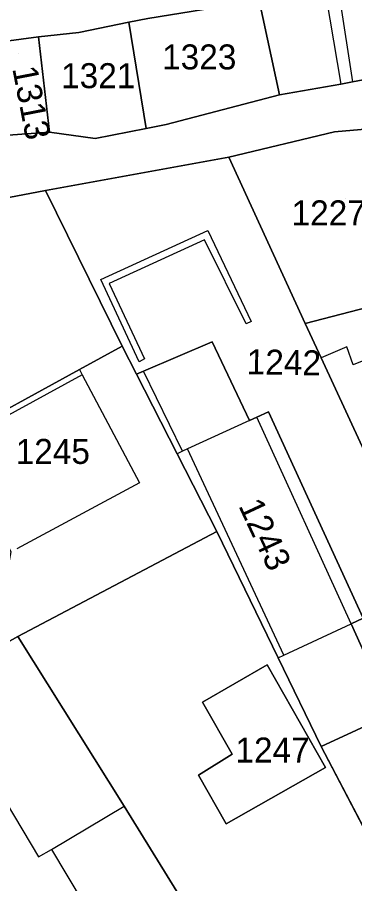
# Model space of a CAD drawing. Extents: x -263943 to -261149, y -1236934 to -1230686.
# Drawn here: x -263034.8 to -263007.8, y -1235384.4 to -1235315.1 of the extents above; entities that cross this region are included whole.
import ezdxf

# ---------------------------------------------------------------- set-up
doc = ezdxf.new("R2010")
doc.units = 0
for name, color, linetype in [('body_kn', 7, 'Continuous'), ('kladpar_druhypozemkov', 7, 'Continuous'), ('kladpar_hranice', 7, 'Continuous'), ('kladpar_parcelnecisla', 7, 'Continuous'), ('kladpar_plochy', 7, 'Continuous'), ('zappar_hrandruhpozemk', 7, 'Continuous')]:
    doc.layers.add(name, color=color, linetype=linetype)

msp = doc.modelspace()

# ---------------------------------------------------------------- linework, layer by layer
at = {"layer": 'body_kn'}
for p, q in [((-263024.4, -1235315.2), (-263024.4, -1235315.2)), ((-263025.91, -1235315.5), (-263025.91, -1235315.5)), ((-263033.14, -1235316.65), (-263033.14, -1235316.65)), ((-263029.91, -1235316.31), (-263029.91, -1235316.31)), ((-263008.93, -1235320.44), (-263008.93, -1235320.44)), ((-263008, -1235320.27), (-263008, -1235320.27)), ((-263008, -1235320.27), (-263008, -1235320.27)), ((-263013.86, -1235321.29), (-263013.86, -1235321.29)), ((-263032.27, -1235324.28), (-263032.27, -1235324.28)), ((-263032.27, -1235324.28), (-263032.27, -1235324.28)), ((-263024.54, -1235323.99), (-263024.54, -1235323.99)), ((-263024.54, -1235323.99), (-263024.54, -1235323.99)), ((-263022.93, -1235323.68), (-263022.93, -1235323.68)), ((-263009.44, -1235324.26), (-263009.44, -1235324.26)), ((-263028.62, -1235324.79), (-263028.62, -1235324.79)), ((-263017.92, -1235326.3), (-263017.92, -1235326.3)), ((-263032.6, -1235328.95), (-263032.6, -1235328.95)), ((-263019.6, -1235332.16), (-263019.6, -1235332.16)), ((-263019.86, -1235332.92), (-263019.86, -1235332.92)), ((-263028.17, -1235336.07), (-263028.17, -1235336.07)), ((-263027.49, -1235336.41), (-263027.49, -1235336.41)), ((-263016.11, -1235339.45), (-263016.11, -1235339.45)), ((-263011.78, -1235339.61), (-263011.78, -1235339.61)), ((-263011.78, -1235339.61), (-263011.78, -1235339.61)), ((-263016.53, -1235339.62), (-263016.53, -1235339.62)), ((-263026.46, -1235341.41), (-263026.46, -1235341.41)), ((-263019.24, -1235341.06), (-263019.24, -1235341.06)), ((-263008.46, -1235341.47), (-263008.46, -1235341.47)), ((-263010.51, -1235342.36), (-263010.51, -1235342.36)), ((-263025.1, -1235342.68), (-263025.1, -1235342.68)), ((-263025.1, -1235342.68), (-263025.1, -1235342.68)), ((-263024.67, -1235342.43), (-263024.67, -1235342.43)), ((-263007.95, -1235342.92), (-263007.95, -1235342.92)), ((-263029.88, -1235343.29), (-263029.88, -1235343.29)), ((-263029.88, -1235343.29), (-263029.88, -1235343.29)), ((-263029.66, -1235343.7), (-263029.66, -1235343.7)), ((-263029.66, -1235343.7), (-263029.66, -1235343.7)), ((-263025.31, -1235343.66), (-263025.31, -1235343.66)), ((-263024.73, -1235343.41), (-263024.73, -1235343.41)), ((-263015.66, -1235347.09), (-263015.66, -1235347.09)), ((-263014.73, -1235346.66), (-263014.73, -1235346.66)), ((-263016.24, -1235347.36), (-263016.24, -1235347.36)), ((-263016.24, -1235347.36), (-263016.24, -1235347.36)), ((-263021.62, -1235349.83), (-263021.62, -1235349.83)), ((-263021.62, -1235349.83), (-263021.62, -1235349.83)), ((-263021.22, -1235349.64), (-263021.22, -1235349.64)), ((-263021.22, -1235349.64), (-263021.22, -1235349.64)), ((-263022.05, -1235350.03), (-263022.05, -1235350.03)), ((-263022.05, -1235350.03), (-263022.05, -1235350.03)), ((-263025.07, -1235352.35), (-263025.07, -1235352.35)), ((-263018.87, -1235356.25), (-263018.87, -1235356.25)), ((-263008.12, -1235363.65), (-263008.12, -1235363.65)), ((-263008.12, -1235363.65), (-263008.12, -1235363.65)), ((-263034.8, -1235364.66), (-263034.8, -1235364.66)), ((-263013.95, -1235366.36), (-263013.95, -1235366.36)), ((-263013.95, -1235366.36), (-263013.95, -1235366.36)), ((-263013.5, -1235366.15), (-263013.5, -1235366.15)), ((-263014.85, -1235366.93), (-263014.85, -1235366.93)), ((-263020.02, -1235369.9), (-263020.02, -1235369.9)), ((-263010.5, -1235373.45), (-263010.5, -1235373.45)), ((-263010.5, -1235373.45), (-263010.5, -1235373.45)), ((-263017.63, -1235374.06), (-263017.63, -1235374.06)), ((-263010.16, -1235375.15), (-263010.16, -1235375.15)), ((-263020.34, -1235375.76), (-263020.34, -1235375.76)), ((-263020.34, -1235375.76), (-263020.34, -1235375.76)), ((-263026.28, -1235378.22), (-263026.28, -1235378.22)), ((-263018.13, -1235379.65), (-263018.13, -1235379.65)), ((-263032.12, -1235381.69), (-263032.12, -1235381.69)), ((-263033.14, -1235382.3), (-263033.14, -1235382.3))]:
    msp.add_line(p, q, dxfattribs=at)
at = {"layer": 'kladpar_druhypozemkov'}
for p, q in [((-263020.36, -1235317.37), (-263020.36, -1235317.37)), ((-263034.75, -1235318.03), (-263034.75, -1235318.03)), ((-263029.56, -1235318.87), (-263029.56, -1235318.87)), ((-263008.57, -1235329.61), (-263008.57, -1235329.61)), ((-263013.46, -1235341.99), (-263013.46, -1235341.99)), ((-263032.34, -1235348.54), (-263032.34, -1235348.54)), ((-263014.11, -1235355.88), (-263014.11, -1235355.88)), ((-263015.04, -1235372.14), (-263015.04, -1235372.14))]:
    msp.add_line(p, q, dxfattribs=at)
at = {"layer": 'kladpar_hranice'}
for points in [[(-263008, -1235320.27), (-263008.93, -1235320.44), (-263013.86, -1235321.29), (-263015.49, -1235313.75), (-263010.22, -1235312.81), (-263002.33, -1235311.36), (-263002.22, -1235312.05), (-263001.13, -1235318.99), (-263008, -1235320.27)], [(-263015.49, -1235313.75), (-263024.4, -1235315.2), (-263025.91, -1235315.5), (-263029.91, -1235316.31), (-263033.14, -1235316.65), (-263036.95, -1235317.16)], [(-263024.54, -1235323.99), (-263025.91, -1235315.5), (-263024.4, -1235315.2), (-263015.49, -1235313.75), (-263013.86, -1235321.29), (-263022.93, -1235323.68), (-263024.54, -1235323.99)], [(-263035.58, -1235324.54), (-263032.27, -1235324.28), (-263028.62, -1235324.79), (-263024.54, -1235323.99), (-263022.93, -1235323.68), (-263013.86, -1235321.29), (-263008.93, -1235320.44), (-263008, -1235320.27), (-263001.13, -1235318.99), (-262996.89, -1235318.14), (-262989.17, -1235316.6), (-262980.34, -1235316.17), (-262972.19, -1235315.65), (-262967.78, -1235315.31), (-262963.87, -1235317.08)], [(-263032.27, -1235324.28), (-263033.14, -1235316.65), (-263029.91, -1235316.31), (-263025.91, -1235315.5), (-263024.54, -1235323.99), (-263028.62, -1235324.79), (-263032.27, -1235324.28)], [(-263035.67, -1235324.12), (-263036.87, -1235317.92), (-263036.95, -1235317.16), (-263033.14, -1235316.65), (-263032.27, -1235324.28), (-263035.58, -1235324.54), (-263035.67, -1235324.12)], [(-262964.37, -1235320.47), (-262977.61, -1235320.74), (-262986.01, -1235321.6), (-262989.92, -1235322.11), (-263003.33, -1235323.74), (-263009.44, -1235324.26), (-263017.92, -1235326.3), (-263032.6, -1235328.95), (-263051.35, -1235332.53)], [(-263011.78, -1235339.61), (-263017.92, -1235326.3), (-263009.44, -1235324.26), (-263003.33, -1235323.74), (-262999.65, -1235335.61), (-262999.65, -1235336.46), (-263011.78, -1235339.61)], [(-263000.82, -1235363.3), (-262999.15, -1235366.91), (-262997.27, -1235369.36), (-263001.69, -1235369.37), (-263004.85, -1235370.83), (-263008.12, -1235363.65), (-263007.14, -1235363.19), (-263014.73, -1235346.66), (-263015.66, -1235347.09), (-263016.24, -1235347.36), (-263019.24, -1235341.06), (-263024.73, -1235343.41), (-263025.31, -1235343.66), (-263026.46, -1235341.41), (-263032.6, -1235328.95), (-263017.92, -1235326.3), (-263011.78, -1235339.61), (-263010.51, -1235342.36), (-263006.23, -1235351.57), (-263000.82, -1235363.3)], [(-263040.01, -1235348.83), (-263042.25, -1235350.05), (-263042.84, -1235348.91), (-263046.17, -1235342.51), (-263048.46, -1235338.09), (-263051.35, -1235332.53), (-263032.6, -1235328.95), (-263026.46, -1235341.41), (-263029.88, -1235343.29), (-263040.01, -1235348.83)], [(-262991.44, -1235359.09), (-262995, -1235360.63), (-263000.38, -1235348.76), (-263001.09, -1235349.1), (-263005.79, -1235351.36), (-263006.23, -1235351.57), (-263010.51, -1235342.36), (-263011.78, -1235339.61), (-262999.65, -1235336.46), (-262998.02, -1235342.31), (-262997.43, -1235342.14), (-262991.44, -1235359.09)], [(-263022.05, -1235350.03), (-263018.87, -1235356.25), (-263034.8, -1235364.66), (-263041.47, -1235368.38), (-263059.41, -1235378.39), (-263061.17, -1235379.37), (-263062.02, -1235377.85), (-263036.34, -1235363.14), (-263035.33, -1235357.88), (-263040.01, -1235348.83), (-263029.88, -1235343.29), (-263026.46, -1235341.41), (-263025.31, -1235343.66), (-263022.05, -1235350.03)], [(-263010.5, -1235373.45), (-263013.95, -1235366.36), (-263018.87, -1235356.25), (-263022.05, -1235350.03), (-263025.31, -1235343.66), (-263024.73, -1235343.41), (-263019.24, -1235341.06), (-263016.24, -1235347.36), (-263015.66, -1235347.09), (-263014.73, -1235346.66), (-263007.14, -1235363.19), (-263008.12, -1235363.65), (-263004.85, -1235370.83), (-263010.5, -1235373.45)], [(-262991.01, -1235421.6), (-263006.36, -1235396.86), (-263012.04, -1235400.51), (-263013.75, -1235397.97), (-263020.74, -1235387.21), (-263026.28, -1235378.22), (-263034.8, -1235364.66), (-263018.87, -1235356.25), (-263013.95, -1235366.36), (-263010.5, -1235373.45), (-262997.36, -1235398.62), (-262985, -1235417.35), (-262988.18, -1235419.6)], [(-263020.74, -1235387.21), (-263031.42, -1235393.24), (-263033.24, -1235390.16), (-263033.97, -1235388.92), (-263033.19, -1235388.4), (-263033.64, -1235387.65), (-263038.57, -1235390.09), (-263039.32, -1235390.46), (-263041.2, -1235387.15), (-263044.76, -1235389.02), (-263046.21, -1235386.56), (-263054.59, -1235391.92), (-263056.98, -1235387.43), (-263061.17, -1235379.37), (-263059.41, -1235378.39), (-263041.47, -1235368.38), (-263034.8, -1235364.66), (-263026.28, -1235378.22), (-263020.74, -1235387.21)], [(-263017.63, -1235374.06), (-263020.34, -1235375.76), (-263018.13, -1235379.65), (-263010.16, -1235375.15), (-263014.85, -1235366.93), (-263020.02, -1235369.9), (-263017.63, -1235374.06)], [(-263020.34, -1235375.76), (-263017.63, -1235374.06), (-263020.02, -1235369.9), (-263014.85, -1235366.93), (-263010.16, -1235375.15), (-263018.13, -1235379.65), (-263020.34, -1235375.76)], [(-262997.36, -1235398.62), (-263010.5, -1235373.45), (-263004.85, -1235370.83), (-263001.69, -1235369.37), (-262995.81, -1235375.55), (-262986.86, -1235391.57), (-262997.36, -1235398.62)]]:
    msp.add_lwpolyline(points, dxfattribs=at)
at = {"layer": 'kladpar_plochy'}
for p, q in [((-263034.8, -1235364.66), (-263018.87, -1235356.25)), ((-263018.87, -1235356.25), (-263013.95, -1235366.36)), ((-263026.28, -1235378.22), (-263034.8, -1235364.66)), ((-263013.95, -1235366.36), (-263010.5, -1235373.45)), ((-263014.85, -1235366.93), (-263020.02, -1235369.9)), ((-263010.16, -1235375.15), (-263014.85, -1235366.93)), ((-263020.02, -1235369.9), (-263017.63, -1235374.06)), ((-263010.5, -1235373.45), (-262997.36, -1235398.62)), ((-263017.63, -1235374.06), (-263020.34, -1235375.76)), ((-263018.13, -1235379.65), (-263010.16, -1235375.15)), ((-263020.34, -1235375.76), (-263018.13, -1235379.65)), ((-263020.74, -1235387.21), (-263026.28, -1235378.22))]:
    msp.add_line(p, q, dxfattribs=at)
for points in [[(-263008, -1235320.27), (-263008.93, -1235320.44), (-263013.86, -1235321.29), (-263015.49, -1235313.75), (-263010.22, -1235312.81), (-263002.33, -1235311.36), (-263002.22, -1235312.05), (-263001.13, -1235318.99)], [(-263024.54, -1235323.99), (-263025.91, -1235315.5), (-263024.4, -1235315.2), (-263015.49, -1235313.75), (-263013.86, -1235321.29), (-263022.93, -1235323.68)], [(-263032.27, -1235324.28), (-263033.14, -1235316.65), (-263029.91, -1235316.31), (-263025.91, -1235315.5), (-263024.54, -1235323.99), (-263028.62, -1235324.79)], [(-263035.67, -1235324.12), (-263036.87, -1235317.92), (-263036.95, -1235317.16), (-263033.14, -1235316.65), (-263032.27, -1235324.28), (-263035.58, -1235324.54)], [(-263011.78, -1235339.61), (-263017.92, -1235326.3), (-263009.44, -1235324.26), (-263003.33, -1235323.74), (-262999.65, -1235335.61), (-262999.65, -1235336.46)], [(-263000.82, -1235363.3), (-262999.15, -1235366.91), (-262997.27, -1235369.36), (-263001.69, -1235369.37), (-263004.85, -1235370.83), (-263008.12, -1235363.65), (-263007.14, -1235363.19), (-263014.73, -1235346.66), (-263015.66, -1235347.09), (-263016.24, -1235347.36), (-263019.24, -1235341.06), (-263024.73, -1235343.41), (-263025.31, -1235343.66), (-263026.46, -1235341.41), (-263032.6, -1235328.95), (-263017.92, -1235326.3), (-263011.78, -1235339.61), (-263010.51, -1235342.36), (-263006.23, -1235351.57)], [(-263040.01, -1235348.83), (-263042.25, -1235350.05), (-263042.84, -1235348.91), (-263046.17, -1235342.51), (-263048.46, -1235338.09), (-263051.35, -1235332.53), (-263032.6, -1235328.95), (-263026.46, -1235341.41), (-263029.88, -1235343.29)], [(-262991.44, -1235359.09), (-262995, -1235360.63), (-263000.38, -1235348.76), (-263001.09, -1235349.1), (-263005.79, -1235351.36), (-263006.23, -1235351.57), (-263010.51, -1235342.36), (-263011.78, -1235339.61), (-262999.65, -1235336.46), (-262998.02, -1235342.31), (-262997.43, -1235342.14)], [(-263022.05, -1235350.03), (-263018.87, -1235356.25), (-263034.8, -1235364.66), (-263041.47, -1235368.38), (-263059.41, -1235378.39), (-263061.17, -1235379.37), (-263062.02, -1235377.85), (-263036.34, -1235363.14), (-263035.33, -1235357.88), (-263040.01, -1235348.83), (-263029.88, -1235343.29), (-263026.46, -1235341.41), (-263025.31, -1235343.66)], [(-263010.5, -1235373.45), (-263013.95, -1235366.36), (-263018.87, -1235356.25), (-263022.05, -1235350.03), (-263025.31, -1235343.66), (-263024.73, -1235343.41), (-263019.24, -1235341.06), (-263016.24, -1235347.36), (-263015.66, -1235347.09), (-263014.73, -1235346.66), (-263007.14, -1235363.19), (-263008.12, -1235363.65), (-263004.85, -1235370.83)], [(-263020.74, -1235387.21), (-263031.42, -1235393.24), (-263033.24, -1235390.16), (-263033.97, -1235388.92), (-263033.19, -1235388.4), (-263033.64, -1235387.65), (-263038.57, -1235390.09), (-263039.32, -1235390.46), (-263041.2, -1235387.15), (-263044.76, -1235389.02), (-263046.21, -1235386.56), (-263054.59, -1235391.92), (-263056.98, -1235387.43), (-263061.17, -1235379.37), (-263059.41, -1235378.39), (-263041.47, -1235368.38), (-263034.8, -1235364.66), (-263026.28, -1235378.22)], [(-263020.34, -1235375.76), (-263017.63, -1235374.06), (-263020.02, -1235369.9), (-263014.85, -1235366.93), (-263010.16, -1235375.15), (-263018.13, -1235379.65)], [(-262997.36, -1235398.62), (-263010.5, -1235373.45), (-263004.85, -1235370.83), (-263001.69, -1235369.37), (-262995.81, -1235375.55), (-262986.86, -1235391.57)]]:
    msp.add_lwpolyline(points, close=True, dxfattribs=at)
for points in [[(-263015.49, -1235313.75), (-263024.4, -1235315.2), (-263025.91, -1235315.5), (-263029.91, -1235316.31), (-263033.14, -1235316.65), (-263036.95, -1235317.16)], [(-263035.58, -1235324.54), (-263032.27, -1235324.28), (-263028.62, -1235324.79), (-263024.54, -1235323.99), (-263022.93, -1235323.68), (-263013.86, -1235321.29), (-263008.93, -1235320.44), (-263008, -1235320.27), (-263001.13, -1235318.99), (-262996.89, -1235318.14), (-262989.17, -1235316.6), (-262980.34, -1235316.17), (-262972.19, -1235315.65), (-262967.78, -1235315.31), (-262963.87, -1235317.08)], [(-262964.37, -1235320.47), (-262977.61, -1235320.74), (-262986.01, -1235321.6), (-262989.92, -1235322.11), (-263003.33, -1235323.74), (-263009.44, -1235324.26), (-263017.92, -1235326.3), (-263032.6, -1235328.95), (-263051.35, -1235332.53)]]:
    msp.add_lwpolyline(points, dxfattribs=at)
at = {"layer": 'zappar_hrandruhpozemk'}
for p, q in [((-263010.11, -1235313.45), (-263008.93, -1235320.44)), ((-263009.09, -1235313.27), (-263008, -1235320.27)), ((-263028.17, -1235336.07), (-263019.6, -1235332.16)), ((-263019.86, -1235332.92), (-263027.49, -1235336.41)), ((-263025.1, -1235342.68), (-263028.17, -1235336.07)), ((-263029.66, -1235343.7), (-263039.43, -1235349.06)), ((-263021.62, -1235349.83), (-263024.73, -1235343.41)), ((-263008.12, -1235363.65), (-263015.66, -1235347.09)), ((-263016.24, -1235347.36), (-263021.22, -1235349.64)), ((-263013.5, -1235366.15), (-263021.22, -1235349.64)), ((-263025.07, -1235352.35), (-263034.9, -1235357.65)), ((-263013.5, -1235366.15), (-263008.12, -1235363.65)), ((-263013.95, -1235366.36), (-263013.5, -1235366.15)), ((-263032.12, -1235381.69), (-263026.28, -1235378.22)), ((-263032.12, -1235381.69), (-263029.57, -1235385.95))]:
    msp.add_line(p, q, dxfattribs=at)
for points in [[(-263019.6, -1235332.16), (-263016.11, -1235339.45), (-263016.53, -1235339.62), (-263019.86, -1235332.92)], [(-263027.49, -1235336.41), (-263024.67, -1235342.43), (-263025.1, -1235342.68)], [(-263004.56, -1235341.55), (-263007.95, -1235342.92), (-263008.46, -1235341.47), (-263010.51, -1235342.36)], [(-263029.88, -1235343.29), (-263029.66, -1235343.7), (-263025.07, -1235352.35)], [(-263021.22, -1235349.64), (-263021.62, -1235349.83), (-263022.05, -1235350.03)], [(-263038.38, -1235373.55), (-263037.69, -1235374.7), (-263033.14, -1235382.3), (-263032.12, -1235381.69)]]:
    msp.add_lwpolyline(points, dxfattribs=at)

# ---------------------------------------------------------------- texts
at = {"layer": 'kladpar_parcelnecisla'}
for s, p in [('1323', (-263023.252, -1235319.27)), ('1321', (-263031.34, -1235320.77)), ('1227/2', (-263012.883, -1235331.75)), ('1245', (-263034.982, -1235350.84)), ('1247', (-263017.38, -1235374.74))]:
    msp.add_text(s, height=2, dxfattribs=at).set_placement(p)
for s, rotation, p in [('1313', 281, (-263035.258, -1235319.191)), ('1242', 359, (-263016.491, -1235343.66)), ('1243', 295, (-263017.167, -1235354.184))]:
    msp.add_text(s, height=2, rotation=rotation, dxfattribs=at).set_placement(p)

doc.saveas('drawing.dxf')
